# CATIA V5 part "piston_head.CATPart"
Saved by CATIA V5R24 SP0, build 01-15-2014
Part number: Part1
Bounding box of the stored display mesh (mm): x -42.5 to 42.5, y -42.342 to 42.342, z 0 to 60
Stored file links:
  D:\OneDrive\01_COURSE WORK\2019-1\CAD\models\piston_head.CATPart
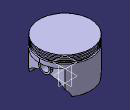
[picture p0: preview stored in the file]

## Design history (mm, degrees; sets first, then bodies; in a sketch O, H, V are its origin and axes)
Body1 (main body)
  Sketch1 on xy-plane, origin (0, 0, 0), H (1, 0, 0), V (0, 1, 0)
    circle A1 centre (0, 0) radius 42.5
    radius A1 = 42.5
  Pad1: profile Sketch1, direction (0, 0, 1), length 60
  Sketch2 on yz-plane, origin (0, 0, 0), H (0, 1, 0), V (0, 0, 1)
    line L1 (47.0894, 58) -> (40, 58)
    line L2 (40, 58) -> (40, 56)
    line L3 (40, 56) -> (47.0894, 56)
    line L4 (47.0894, 56) -> (47.0894, 54)
    line L5 (47.0894, 54) -> (40, 54)
    point P6 (40, 54)
    line L6 (40, 54) -> (40, 52)
    line L7 (40, 52) -> (47.0894, 52)
    point P8 (47.0894, 52)
    line L8 (47.0894, 52) -> (47.0894, 50)
    line L9 (47.0894, 50) -> (40, 50)
    point P10 (40, 50)
    line L10 (40, 50) -> (40, 47)
    line L11 (40, 47) -> (47.0894, 47)
    point P12 (47.0894, 47)
    axis line L12 (0, 72.95) -> (0, -22.7727)
    point P13 (0, 72.95)
    reference projected line E1 (-42.5, 60) -> (42.5, 60) from edge [face of Pad1 from Sketch1.A1 | end face of Pad1]
    distance L1 E1 = 2
    distance L1 L3 = 2
    distance L3 L5 = 2
    distance L5 L7 = 2
    distance L7 L9 = 2
    distance L9 L11 = 3
    distance L2 V = 40
    horizontal: L1 H, L3 H, L5 H, L7 H, L9 H, L11 H
    vertical: L2 V, L4 V, L6 V, L8 V, L10 V, L12 V
    coincidence: P6 L2, P8 L4, P10 L2, P12 L4, P13 V
  Groove1: profile Sketch2, axis Sketch2.L12, angle 360
  Sketch3 on yz-plane, origin (0, 0, 0), H (0, 1, 0), V (0, 0, 1)
    ellipse A1 centre (0, 0) semi-axes 35, 20 rotation 0
    "Radius" A1 = 35
    "Radius" A1 = 20
    angle A1 H = 0
  Pocket1: profile Sketch3, direction (-1, 0, 0), through (limit type 3), opposite side through (limit type 3)
  Sketch4 on zx-plane, origin (0, 0, 0), H (-1, 0, 0), V (0, 0, 1)
    line L1 (46.2876, 40) -> (30, 40)
    line L2 (30, 40) -> (30, -4.3009)
    reference projected line E2 (42.5, 20) -> (42.5, 47) from face of Pad1 from Sketch1.A1
    reference projected line E3 (42.5, 47) -> (-42.5, 47) from edge [face of Groove1 from Sketch2.L11 | face of Pad1 from Sketch1.A1]
    distance L2 E2 = 12.5
    distance L1 E3 = 7
    horizontal: L1 H
    vertical: L2 V
  Pocket2: profile Sketch4, direction (0, -1, 0), through (limit type 3), opposite side through (limit type 3)
  Mirror1: of Pocket2, about yz-plane
  Body2
    Sketch5 on xy-plane, origin (0, 0, 0), H (1, 0, 0), V (0, 1, 0)
      circle A1 centre (0, 0) radius 35
      radius A1 = 35
    Pad2: profile Sketch5, direction (0, 0, 1), length 55, opposite side length -45
    Sketch6 on start face of Pad2, origin (0, 0, 45), H (1, 0, 0), V (0, -1, 0)
      line L1 (20, -28.7228) -> (20, 28.7228)
      point P2 (20, 28.7228)
      arc A1 centre (0, 0) radius 35 from (20, 28.7228) to (-20, 28.7228) ccw
      point P4 (0, 35)
      point P5 (-20, 28.7228)
      line L2 (-20, 28.7228) -> (-20, -28.7228)
      arc A2 centre (0, 0) radius 35 from (-20, -28.7228) to (20, -28.7228) ccw
      point P8 (0, -35)
      reference intersected line E1 through (30, 0) direction (0, -1) from face of Mirror1
      reference projected line E2 (24.1091, 35) -> (-24.1091, 35) from edge [start face of Pad1 | face of Pocket1 from Sketch3.A1]
      distance L1 E1 = 10
      radius A1 = 35
      vertical: L1 V, L2 V
      coincidence: A1 P4, P4 V, A2 P8, P8 V
      symmetry: L1 L2 V, P2 P5 V, A1 A2 H
      tangency: A1 E2
    Pad3: profile Sketch6, direction (0, 0, -1), length 55
  Remove1: tool Body2
  Body3
    Sketch7 on yz-plane, origin (0, 0, 0), H (0, 1, 0), V (0, 0, 1)
      circle A1 centre (0, 30) radius 10
      point P1 (0, 30)
      reference projected line E1 (30.104, 40) -> (-30.104, 40) from edge [face of Pad1 from Sketch1.A1 | face of Mirror1]
      circle A2 centre (0, 30) radius 7.5
      radius A1 = 10
      radius A2 = 7.5
      coincidence: P1 V
      tangency: A1 E1
    Pad4: profile Sketch7, direction (1, 0, 0), length 34, opposite side length -10
    Mirror2: of Pad4, about yz-plane
    Plane1: type Offset, RefPlane xy-plane, Offset 20
    Sketch8 on Plane1, origin (-3.1836, -0.9006, 20), H (1, 0, 0), V (0, 1, 0)
      point P1 (-11.8164, 0.9006)
      reference projected line E1 (-6.8164, 10.9006) -> (-6.8164, -9.0994) from edge [face of Mirror2 | face of Mirror2]
      reference projected line E2 through (0, 0.9006) direction (1, 0) from axis of face of Mirror2
      distance P1 E1 = 5
      coincidence: P1 E2
    Hole1: placed by Sketch8, at (-15, 0, 20) direction (0, 0, 1), diameter 3, through (limit type 6), counterbore diameter 4, counterbore depth 1
  Trim1: tool Body3
  Sketch9 on yz-plane, origin (0, 0, 0), H (0, 1, 0), V (0, 0, 1)
    line L1 (-35, 45) -> (-25, 55)
    point P1 (-35, 45)
    point P2 (-25, 55)
    angle L1 V = 135 (reference)
    distance P2 V = 25
    distance P1 H = 45
    distance P2 H = 55
    distance P1 V = 35
  Stiffener1: ExtendedProfile Sketch9, ThicknessTop 0, ThicknessValue 4
  Mirror3: of Stiffener1, about zx-plane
